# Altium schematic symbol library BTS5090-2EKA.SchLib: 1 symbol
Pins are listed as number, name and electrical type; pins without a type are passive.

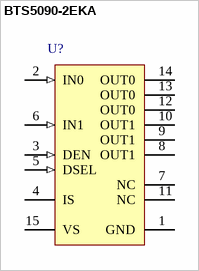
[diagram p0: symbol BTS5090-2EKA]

## BTS5090-2EKA
designator U?
PROFET+ 12 V Smart High-Side Power Switch, 90 mOhm, 2 Channels, 2.5 A Load Current, -40 to 150 degC, PG-DSO-14-40, Reel, Green; Manufacturer: Infineon; PartNumber: BTS5090-2EKA; Channels: 2; Green: TRUE; Group: Automotive Qualified; Load Current (typ): 2.5 A; Ptot (max): 1.9 W; Recommended Operating Voltage Max.: 28 V; Recommended Operating Voltage Min.: 5 V; RON @ 25degreesC: 90 mOhm; RON(max) @ 150degreesC: 180 mOhm; toff (max): 230 us
footprint INF-PG-DSO-14-40_N (SOP, 14-Leads, Body 8.65x3.9mm, Pitch 1.27mm, Thermal Pad 6.5x2.75mm, IPC Medium Density)
footprint INF-PG-DSO-14-40_L (SOP, 14-Leads, Body 8.65x3.9mm, Pitch 1.27mm, Thermal Pad 6.5x2.75mm, IPC High Density)
footprint INF-PG-DSO-14-40_M (SOP, 14-Leads, Body 8.65x3.9mm, Pitch 1.27mm, Thermal Pad 6.5x2.6mm, IPC Low Density)
pins: 1 GND (power) "GrouND; Ground connection", 2 IN0 (in) "INput channel 0; Input signal for channel 0 activation", 3 DEN (in) "Diagnostic ENable; Digital signal to enable/disable the diagnosis of the device", 4 IS (hiz) "Sense; Sense current of the selected channel", 5 DSEL (in) "Diagnostic SELection; Digital signal to select the channel to be diagnosed", 6 IN1 (in) "INput channel 1; Input signal for channel 1 activation", 7 NC "Not Connected; No internal connection to the chip", 8 OUT1 (power) "OUTput 1; Protected high side power output channel 1", 9 OUT1 (power) "OUTput 1; Protected high side power output channel 1", 10 OUT1 (power) "OUTput 1; Protected high side power output channel 1", 11 NC "Not Connected; No internal connection to the chip", 12 OUT0 (power) "OUTput 0; Protected high side power output channel 0", 13 OUT0 (power) "OUTput 0; Protected high side power output channel 0", 14 OUT0 (power) "OUTput 0; Protected high side power output channel 0", 15 VS (power) "Voltage Supply; Battery voltage"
